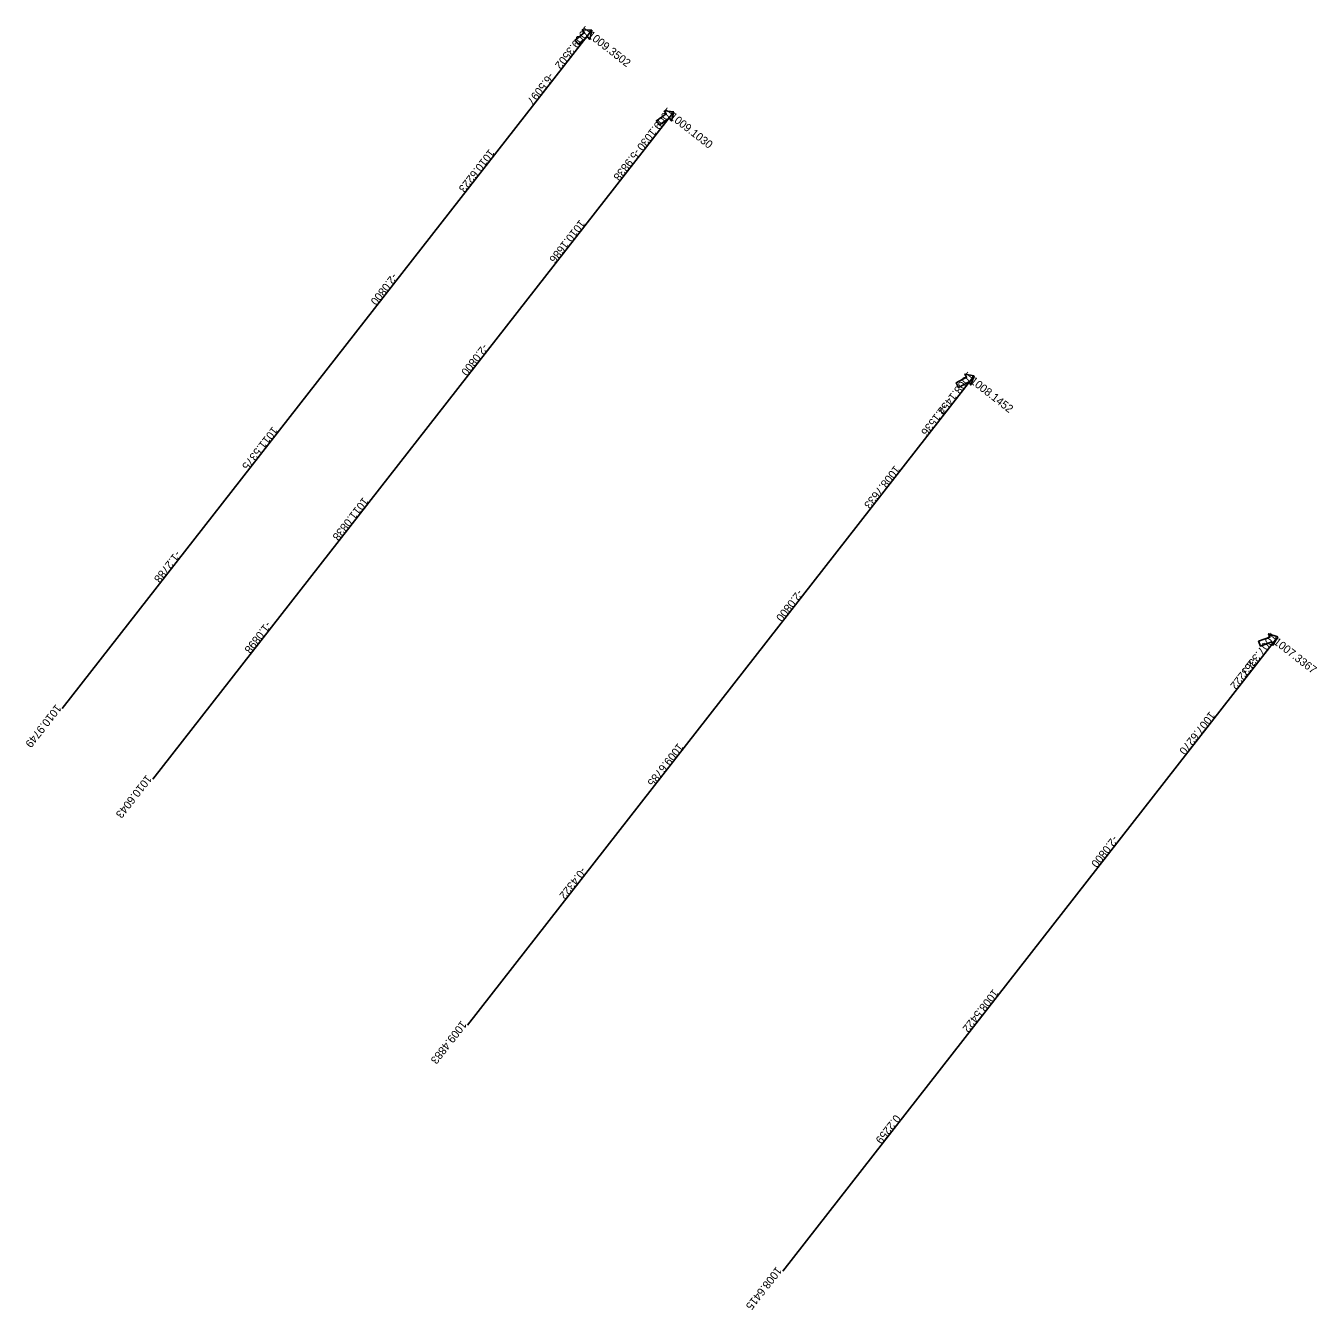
# Model space of a CAD drawing. Extents: x 4435 to 1613579, y 3750 to 1095560.
# Drawn here: x 1609337 to 1609498.3, y 1092022.5 to 1092183 of the extents above; entities that cross this region are included whole.
import ezdxf

# ---------------------------------------------------------------- set-up
doc = ezdxf.new("R2010")
doc.units = 0
doc.layers.add('Default', color=7, linetype='Continuous')

msp = doc.modelspace()

# ---------------------------------------------------------------- linework, layer by layer
at = {"layer": 'Default'}
for p, q in [((1609407.68, 1092182.44), (1609341.5, 1092097.67)), ((1609417.92, 1092172.25), (1609352.81, 1092088.84)), ((1609455.45, 1092139.23), (1609392.15, 1092058.13)), ((1609493.36, 1092106.63), (1609431.52, 1092027.4))]:
    msp.add_line(p, q, dxfattribs=at)
for points in [[(1609407.68, 1092182.44), (1609406.48, 1092182.48), (1609406.75, 1092182.13), (1609405.57, 1092181.2), (1609405.97, 1092180.7), (1609407.15, 1092181.62), (1609407.43, 1092181.27)], [(1609417.92, 1092172.25), (1609416.72, 1092172.35), (1609416.98, 1092171.98), (1609415.75, 1092171.12), (1609416.12, 1092170.6), (1609417.35, 1092171.46), (1609417.61, 1092171.09)], [(1609455.45, 1092139.23), (1609454.28, 1092139.47), (1609454.49, 1092139.08), (1609453.18, 1092138.36), (1609453.48, 1092137.79), (1609454.8, 1092138.51), (1609455.02, 1092138.12)], [(1609493.36, 1092106.63), (1609492.23, 1092107.03), (1609492.39, 1092106.61), (1609490.98, 1092106.09), (1609491.2, 1092105.49), (1609492.61, 1092106.01), (1609492.77, 1092105.58)]]:
    msp.add_lwpolyline(points, close=True, dxfattribs=at)

# ---------------------------------------------------------------- texts
for s, rotation, p in [('1009.3502', 232.0256, (1609406.89, 1092183.06)), ('1009.3502', 322.0256, (1609407.06, 1092181.65)), ('-6.5097', 232.0256, (1609402.31, 1092177.2)), ('1009.1030', 232.0256, (1609417.13, 1092172.86)), ('1009.1030', 322.0256, (1609417.3, 1092171.46)), ('1010.6223', 232.0256, (1609394.86, 1092167.65)), ('-5.9838', 232.0256, (1609413.09, 1092167.69)), ('1010.1686', 232.0256, (1609406.17, 1092158.83)), ('-2.0800', 232.0256, (1609382.76, 1092152.15)), ('-2.0800', 232.0256, (1609394.07, 1092143.33)), ('1008.1452', 232.0256, (1609454.67, 1092139.85)), ('1008.1452', 322.0256, (1609454.84, 1092138.44)), ('-4.1536', 232.0256, (1609451.53, 1092135.83)), ('1011.5375', 232.0256, (1609367.79, 1092132.97)), ('1008.7633', 232.0256, (1609445.51, 1092128.12)), ('1011.0838', 232.0256, (1609379.1, 1092124.14)), ('-1.2788', 232.0256, (1609355.69, 1092117.47)), ('-2.0800', 232.0256, (1609433.41, 1092112.62)), ('-1.0898', 232.0256, (1609367, 1092108.64)), ('1007.3367', 232.0256, (1609492.57, 1092107.24)), ('1007.3367', 322.0256, (1609492.75, 1092105.84)), ('-2.3222', 232.0256, (1609490.16, 1092104.15)), ('1010.9749', 232.0256, (1609340.72, 1092098.28)), ('1007.6270', 232.0256, (1609484.88, 1092097.39)), ('1009.6785', 232.0256, (1609418.44, 1092093.43)), ('1010.6043', 232.0256, (1609352.02, 1092089.46)), ('-2.0800', 232.0256, (1609472.78, 1092081.89)), ('-0.4322', 232.0256, (1609406.34, 1092077.93)), ('1008.5422', 232.0256, (1609457.81, 1092062.7)), ('1009.4883', 232.0256, (1609391.36, 1092058.75)), ('0.2259', 232.0256, (1609445.57, 1092047.02)), ('1008.6415', 232.0256, (1609430.73, 1092028.02))]:
    msp.add_text(s, height=1, rotation=rotation, dxfattribs=at).set_placement(p)

doc.saveas('drawing.dxf')
